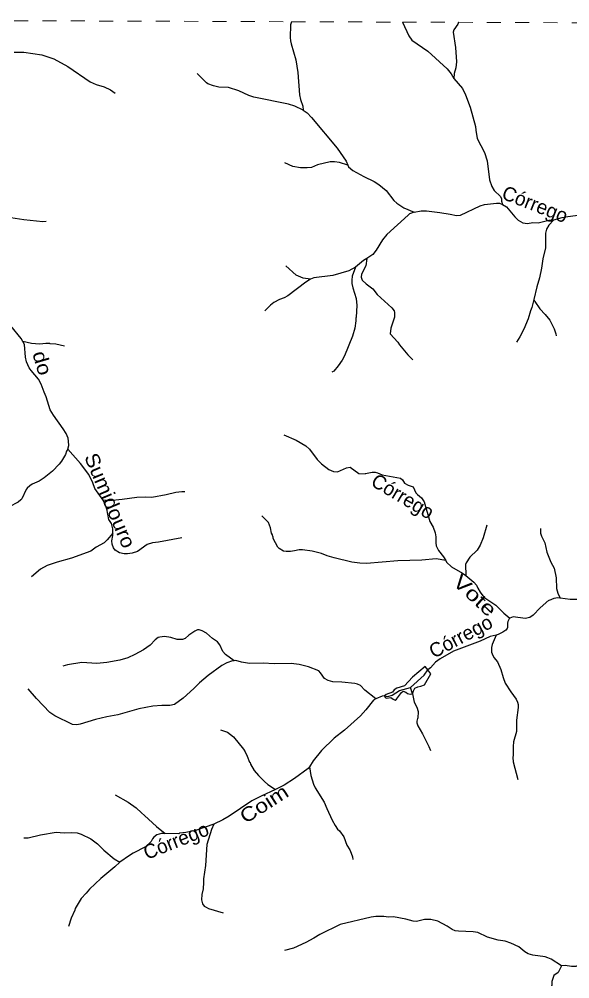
# Model space of a CAD drawing. Extents: x 551.6 to 577.6, y 7567 to 7594.7.
# Drawn here: x 554.66 to 558.55, y 7587.95 to 7594.73 of the extents above; entities that cross this region are included whole.
import ezdxf
from ezdxf.enums import TextEntityAlignment as Align

# ---------------------------------------------------------------- set-up
doc = ezdxf.new("R2010")
doc.units = 0
doc.header["$LTSCALE"] = 0.04
doc.linetypes.add('SHORT_DASHED', pattern=[2.7, 1.5, -1.2])
for name, color, linetype, lineweight in [('2', 7, 'Continuous', 25), ('53', 7, 'SHORT_DASHED', 13), ('55', 7, 'Continuous', 25), ('7', 7, 'Continuous', 25)]:
    doc.layers.add(name, color=color, linetype=linetype, lineweight=lineweight)
doc.layers.add('61', color=7, linetype='Continuous')

msp = doc.modelspace()

# ---------------------------------------------------------------- linework, layer by layer
at = {"layer": '2'}
msp.add_line((557.5713, 7590.1064), (557.5493, 7590.1345), dxfattribs=at)
for points in [[(557.5493, 7590.1345), (557.5317, 7590.1571), (557.4418, 7590.0815), (557.3847, 7590.0219), (557.3307, 7590.0034), (557.3108, 7589.9927), (557.2997, 7589.9763), (557.2557, 7589.9592), (557.2445, 7589.9499)], [(557.4425, 7589.9644), (557.4481, 7589.9864), (557.4578, 7590.005), (557.4779, 7590.0146), (557.4997, 7590.0179), (557.5255, 7590.0292), (557.5713, 7590.1064)], [(557.2445, 7589.9499), (557.2476, 7589.9376), (557.2587, 7589.9331), (557.2885, 7589.9383), (557.3041, 7589.9264), (557.3195, 7589.9208), (557.3284, 7589.9275), (557.3626, 7589.9751), (557.376, 7589.9841), (557.3939, 7589.9766), (557.4058, 7589.9662), (557.4244, 7589.9625), (557.4425, 7589.9644)]]:
    msp.add_lwpolyline(points, dxfattribs=at)
at = {"layer": '53'}
msp.add_lwpolyline([(551.6503, 7578.541), (551.6589, 7581.176), (551.6615, 7581.9586), (551.6634, 7582.5573), (551.6645, 7582.8996), (551.6852, 7589.2613), (551.6863, 7589.5882), (551.6896, 7590.6141), (551.6917, 7591.2598), (551.6958, 7592.5139), (551.6971, 7592.9033), (551.701, 7594.113), (551.703, 7594.7296), (552.7903, 7594.7256), (553.4424, 7594.7233), (554.6279, 7594.7189), (556.5859, 7594.7118), (557.3702, 7594.7089), (557.7663, 7594.7075), (559.9893, 7594.6994)], dxfattribs=at)
at = {"layer": '55'}
msp.add_line((557.4425, 7589.9644), (557.4269, 7590.0083), dxfattribs=at)
for points in [[(557.4269, 7590.0083), (557.5233, 7590.0957), (557.549, 7590.1343)], [(557.2445, 7589.9499), (557.2669, 7589.9451), (557.2974, 7589.954), (557.3502, 7589.9883), (557.4269, 7590.0083)]]:
    msp.add_lwpolyline(points, dxfattribs=at)
at = {"layer": '7'}
for points in [[(556.5859, 7594.7118), (556.579, 7594.689), (556.5782, 7594.6004), (556.5806, 7594.5779), (556.5839, 7594.5554), (556.6177, 7594.4427), (556.6305, 7594.3526), (556.6434, 7594.1964), (556.6499, 7594.1626), (556.666, 7594.1143), (556.668, 7594.088)], [(557.3702, 7594.7089), (557.416, 7594.6117), (557.4378, 7594.5819), (557.5504, 7594.503), (557.6864, 7594.3799), (557.7146, 7594.3437), (557.7339, 7594.311)], [(557.7663, 7594.7075), (557.7613, 7594.6954), (557.7331, 7594.6535), (557.7283, 7594.6375), (557.7444, 7594.5296), (557.7532, 7594.4282), (557.7476, 7594.3864), (557.7347, 7594.3469), (557.7339, 7594.311)], [(554.6282, 7594.4974), (554.6958, 7594.4974), (554.8246, 7594.4781), (554.9075, 7594.4507), (555.0065, 7594.3944), (555.1642, 7594.2874), (555.2077, 7594.268), (555.264, 7594.252), (555.3091, 7594.2302), (555.3421, 7594.2077)], [(556.668, 7594.088), (556.6096, 7594.1143), (556.5646, 7594.1304), (556.3199, 7594.1787), (556.2861, 7594.1908), (556.2137, 7594.2238), (556.1412, 7594.2463), (556.0736, 7594.2487), (556.035, 7594.2584), (555.9964, 7594.2737), (555.9875, 7594.2801), (555.9199, 7594.3453)], [(557.7339, 7594.311), (557.7951, 7594.2399), (557.8168, 7594.1948), (557.849, 7594.1079), (557.886, 7593.9711), (557.8876, 7593.9453)], [(556.668, 7594.088), (556.6973, 7594.0676), (556.7279, 7594.0355), (556.909, 7593.8182)], [(557.8876, 7593.9453), (557.8989, 7593.8874), (557.9488, 7593.7884), (557.9681, 7593.7297), (557.9858, 7593.5961), (558.0019, 7593.5478), (558.0188, 7593.5188), (558.0631, 7593.4777), (558.0695, 7593.4608), (558.0695, 7593.4448), (558.0773, 7593.4201)], [(556.909, 7593.8182), (556.9718, 7593.7272), (556.9843, 7593.6994)], [(556.9843, 7593.6994), (556.9251, 7593.7168), (556.8897, 7593.7216), (556.8607, 7593.7216), (556.7706, 7593.7015), (556.7271, 7593.683), (556.6982, 7593.6789), (556.6499, 7593.6789), (556.5952, 7593.6886), (556.5396, 7593.7152)], [(556.9843, 7593.6994), (556.9895, 7593.6878), (557.0201, 7593.662), (557.0973, 7593.6186), (557.1698, 7593.5832), (557.2044, 7593.5614), (557.2551, 7593.5188), (557.309, 7593.448), (557.3299, 7593.4294), (557.3798, 7593.3981), (557.4531, 7593.3675)], [(557.7074, 7593.3514), (557.7525, 7593.3433), (557.7814, 7593.3449), (557.9199, 7593.4109), (557.9488, 7593.4198), (558.0357, 7593.4311), (558.0551, 7593.4294), (558.0773, 7593.4201)], [(554.8544, 7593.2999), (554.8294, 7593.2991), (554.6974, 7593.3119), (554.5751, 7593.3321), (554.5091, 7593.3313), (554.4158, 7593.3192), (554.3192, 7593.3111), (554.295, 7593.3144), (554.1517, 7593.3627)], [(557.4531, 7593.3675), (557.4209, 7593.3546), (557.4096, 7593.3465), (557.2607, 7593.2089), (557.2301, 7593.1711), (557.185, 7593.0987), (557.1601, 7593.0673), (557.1191, 7593.0385)], [(557.4531, 7593.3675), (557.5014, 7593.3763), (557.54, 7593.3763), (557.635, 7593.3651), (557.7074, 7593.3514)], [(558.0773, 7593.4201), (558.1041, 7593.4045), (558.1645, 7593.3345), (558.1887, 7593.3111), (558.2208, 7593.2918), (558.253, 7593.2854), (558.2901, 7593.2942), (558.3287, 7593.2902), (558.4043, 7593.3095), (558.4398, 7593.3133)], [(558.5379, 7593.3353), (558.6474, 7593.3498), (558.6715, 7593.3578), (558.7053, 7593.3755), (558.7343, 7593.382), (558.7496, 7593.382), (558.8228, 7593.3465), (558.8518, 7593.3417), (558.8808, 7593.3433), (558.9267, 7593.3549), (558.9452, 7593.3578)], [(558.4398, 7593.3133), (558.4051, 7593.2749), (558.3874, 7593.2468), (558.3818, 7593.2194), (558.3802, 7593.1148), (558.3617, 7593.0375), (558.3528, 7592.9699), (558.3383, 7592.9039), (558.319, 7592.8395), (558.2975, 7592.7506)], [(558.4398, 7593.3133), (558.4993, 7593.3296), (558.5379, 7593.3353)], [(557.1191, 7593.0385), (557.0957, 7593.0246), (557.0383, 7592.9781)], [(557.1191, 7593.0385), (557.1118, 7592.9876), (557.0812, 7592.9297), (557.0796, 7592.9071), (557.086, 7592.887), (557.1151, 7592.8596), (557.1609, 7592.8259), (557.1915, 7592.784), (557.2953, 7592.6898), (557.3114, 7592.6689), (557.3146, 7592.6577), (557.3146, 7592.6239), (557.2873, 7592.5466), (557.284, 7592.508), (557.3372, 7592.4484), (557.3484, 7592.4307), (557.408, 7592.3583), (557.4426, 7592.3237)], [(556.7215, 7592.8942), (556.6692, 7592.8999), (556.6193, 7592.9208), (556.5461, 7592.9868)], [(557.0383, 7592.9781), (556.9911, 7592.953), (556.8784, 7592.92), (556.7448, 7592.9023), (556.7215, 7592.8942)], [(557.0383, 7592.9781), (557.0152, 7592.9136), (557.012, 7592.8862), (557.0136, 7592.8621), (557.0201, 7592.8331), (557.0426, 7592.7558), (557.0474, 7592.7076), (557.0442, 7592.6247), (557.041, 7592.6174), (557.0418, 7592.5997), (557.0329, 7592.5466), (557.0185, 7592.4903), (556.9621, 7592.3518), (556.9444, 7592.3204), (556.9154, 7592.2802), (556.8865, 7592.244), (556.8728, 7592.2359)], [(554.6901, 7592.4524), (554.6765, 7592.4749), (554.6057, 7592.5627), (554.5067, 7592.6472), (554.4672, 7592.6931), (554.4109, 7592.747), (554.3546, 7592.7896), (554.2403, 7592.8677), (554.15, 7592.9437)], [(556.7215, 7592.8942), (556.6885, 7592.8733), (556.5597, 7592.7751), (556.534, 7592.7615), (556.5018, 7592.7502), (556.4615, 7592.7277)], [(556.4615, 7592.7277), (556.4374, 7592.7108), (556.398, 7592.6697)], [(558.2975, 7592.7506), (558.2836, 7592.6931), (558.2739, 7592.6689), (558.2587, 7592.6126), (558.2281, 7592.5402), (558.1999, 7592.4854), (558.1766, 7592.4492)], [(558.2975, 7592.7506), (558.3045, 7592.7349), (558.3399, 7592.6834), (558.3786, 7592.6448), (558.4124, 7592.6045), (558.4414, 7592.5425), (558.4534, 7592.5064), (558.455, 7592.4927)], [(554.7087, 7592.3422), (554.7022, 7592.4323), (554.6901, 7592.4524)], [(554.9831, 7592.4194), (554.9228, 7592.4331), (554.8833, 7592.4363), (554.8809, 7592.4395), (554.852, 7592.4395), (554.8085, 7592.4339), (554.7795, 7592.4355), (554.7505, 7592.4387), (554.6901, 7592.4524)], [(555.007, 7591.6931), (555.0152, 7591.7177), (555.0129, 7591.7482), (555.0097, 7591.7692), (554.9952, 7591.803), (554.9751, 7591.8368), (554.9067, 7591.9317), (554.8833, 7591.9704), (554.8543, 7592.0621), (554.8391, 7592.0959), (554.8197, 7592.1522), (554.8004, 7592.186), (554.7473, 7592.2488), (554.7344, 7592.2681), (554.7151, 7592.3084), (554.7087, 7592.3422)], [(556.5332, 7591.7949), (556.6193, 7591.7555), (556.6877, 7591.7152), (556.7134, 7591.6919), (556.7674, 7591.6203), (556.7979, 7591.5881), (556.8495, 7591.5486), (556.8833, 7591.5341), (556.9106, 7591.5325), (556.975, 7591.5615), (557.0008, 7591.5663), (557.0619, 7591.5213), (557.107, 7591.5188), (557.1086, 7591.5213), (557.1569, 7591.5293), (557.1778, 7591.5293), (557.1939, 7591.5261), (557.2277, 7591.5116), (557.3565, 7591.4882)], [(555.007, 7591.6931), (554.9976, 7591.6774), (554.9896, 7591.6549), (554.963, 7591.6082), (554.9469, 7591.5864), (554.8986, 7591.5382), (554.8391, 7591.4899), (554.8037, 7591.4673), (554.7562, 7591.4456), (554.7393, 7591.4343), (554.7199, 7591.4167), (554.7135, 7591.407), (554.6821, 7591.3426), (554.6749, 7591.3345), (554.6572, 7591.3193), (554.5936, 7591.2863), (554.5735, 7591.2654), (554.5606, 7591.2428), (554.5477, 7591.201), (554.5397, 7591.1623), (554.5389, 7591.1237), (554.5123, 7591.0464), (554.4978, 7590.9869), (554.493, 7590.9507)], [(555.2578, 7591.3329), (555.198, 7591.4142), (555.1843, 7591.4553), (555.1545, 7591.5132), (555.0974, 7591.5913), (555.007, 7591.6931)], [(557.3565, 7591.4882), (557.3709, 7591.4762), (557.3846, 7591.4521), (557.4112, 7591.4376), (557.445, 7591.4263), (557.4643, 7591.3853), (557.4756, 7591.3716), (557.5038, 7591.349), (557.5247, 7591.3201), (557.5633, 7591.1817), (557.5883, 7591.1414), (557.6011, 7591.1028), (557.606, 7591.0738), (557.606, 7591.032), (557.6092, 7591.0094), (557.6261, 7590.9772), (557.6607, 7590.9314), (557.6763, 7590.9052)], [(555.8346, 7591.3909), (555.8113, 7591.3917), (555.7694, 7591.3861), (555.7018, 7591.3692), (555.6004, 7591.3523), (555.5553, 7591.3547), (555.4942, 7591.3523), (555.3912, 7591.3362), (555.2994, 7591.3289), (555.2578, 7591.3329)], [(555.3252, 7591.1003), (555.3252, 7591.1301), (555.3155, 7591.1672), (555.2962, 7591.1953), (555.2817, 7591.2718), (555.2688, 7591.3056), (555.2578, 7591.3329)], [(556.608, 7590.9756), (556.5791, 7590.9692), (556.5501, 7590.9692), (556.5308, 7590.9724), (556.5002, 7590.9901), (556.4913, 7591.0014), (556.4583, 7591.0625), (556.4583, 7591.0746), (556.4551, 7591.0754), (556.4535, 7591.0867), (556.4454, 7591.0988), (556.4374, 7591.1366), (556.4237, 7591.1752), (556.3762, 7591.2211)], [(557.9657, 7591.1567), (557.9416, 7591.0658), (557.919, 7591.0143), (557.8973, 7590.9796), (557.8474, 7590.9305), (557.8192, 7590.8887), (557.8168, 7590.879), (557.8184, 7590.7999)], [(558.3448, 7591.1326), (558.3448, 7591.0996), (558.352, 7591.077), (558.3753, 7591.032), (558.389, 7590.9644), (558.4188, 7590.8951), (558.4413, 7590.8533), (558.4566, 7590.7841), (558.459, 7590.7084), (558.4687, 7590.6746), (558.4841, 7590.6393)], [(555.3252, 7591.1003), (555.2849, 7591.0521), (555.2632, 7591.0311), (555.2061, 7590.9998), (555.169, 7590.9732), (555.0322, 7590.9225), (554.9308, 7590.8951), (554.86, 7590.8718), (554.8133, 7590.8452), (554.7513, 7590.7913)], [(555.8121, 7591.0658), (555.6471, 7591.036), (555.6052, 7591.0311), (555.5666, 7591.0199), (555.499, 7590.9708), (555.4604, 7590.9579), (555.4282, 7590.9523), (555.404, 7590.9531), (555.3719, 7590.9595), (555.3413, 7590.9804), (555.33, 7590.9949), (555.3203, 7591.0207), (555.3179, 7591.0448), (555.3251, 7591.0826), (555.3252, 7591.1003)], [(557.6763, 7590.9052), (557.6076, 7590.9177), (557.5078, 7590.9096), (557.3372, 7590.9048), (557.1167, 7590.8855), (557.0684, 7590.8871), (557.0136, 7590.8935), (556.8881, 7590.9241), (556.8382, 7590.9386), (556.798, 7590.9547), (556.732, 7590.9724), (556.6644, 7590.982), (556.6418, 7590.982), (556.608, 7590.9756)], [(557.6763, 7590.9052), (557.6824, 7590.8951), (557.7162, 7590.8605), (557.7943, 7590.8179), (557.8184, 7590.7999)], [(557.8184, 7590.7999), (557.8756, 7590.7527), (557.8933, 7590.731), (557.9037, 7590.71)], [(557.9037, 7590.71), (557.9182, 7590.6819), (557.9456, 7590.6472), (558.0309, 7590.5909), (558.0872, 7590.5338), (558.1283, 7590.5)], [(558.4841, 7590.6393), (558.4687, 7590.6424), (558.4398, 7590.6384), (558.4075, 7590.6239), (558.4046, 7590.625), (558.3424, 7590.5724), (558.2941, 7590.5201), (558.2691, 7590.504), (558.2369, 7590.4976), (558.1532, 7590.5088), (558.1283, 7590.5), (558.1243, 7590.4935)], [(558.8969, 7590.5024), (558.8679, 7590.504), (558.8389, 7590.5137), (558.8083, 7590.5281), (558.7713, 7590.5571), (558.7118, 7590.5611), (558.6932, 7590.5748), (558.6747, 7590.6006), (558.6595, 7590.6159), (558.6273, 7590.632), (558.554, 7590.6312), (558.4841, 7590.6393)], [(558.1243, 7590.4935), (558.1146, 7590.475), (558.1122, 7590.4638), (558.113, 7590.4332), (558.1098, 7590.4251), (558.1001, 7590.4138), (558.0792, 7590.3994), (558.0454, 7590.3825), (558.0322, 7590.3794)], [(556.1817, 7590.1986), (556.1203, 7590.2433), (556.1018, 7590.2642), (556.0817, 7590.31), (556.064, 7590.3318), (556.0294, 7590.3543), (555.9867, 7590.3937), (555.9561, 7590.4098), (555.9352, 7590.4163), (555.9239, 7590.4155), (555.903, 7590.4074), (555.8612, 7590.3784), (555.8354, 7590.3551), (555.8169, 7590.3479), (555.7791, 7590.3479), (555.734, 7590.3623), (555.6906, 7590.3688), (555.6568, 7590.3656), (555.6455, 7590.3615), (555.6245, 7590.3471), (555.5875, 7590.3076), (555.5425, 7590.2746), (555.4797, 7590.2424), (555.4298, 7590.2199), (555.3735, 7590.203), (555.2817, 7590.1869)], [(558.0322, 7590.3794), (557.9907, 7590.3696), (557.9199, 7590.3358), (557.7299, 7590.265), (557.6366, 7590.2118), (557.6044, 7590.1877), (557.5673, 7590.1483), (557.5493, 7590.1345), (557.549, 7590.1343)], [(558.0322, 7590.3794), (558.0035, 7590.3125), (558.0003, 7590.2915), (558.0003, 7590.2577), (558.0035, 7590.2465), (558.0164, 7590.2223), (558.0414, 7590.1901), (558.0647, 7590.137), (558.0808, 7590.0791), (558.0961, 7590.0388), (558.1347, 7589.9785), (558.1725, 7589.9277), (558.1838, 7589.9068), (558.187, 7589.8891), (558.187, 7589.8682), (558.1758, 7589.7797), (558.1758, 7589.6992), (558.1548, 7589.6252), (558.1516, 7589.593), (558.1516, 7589.5318)], [(555.2817, 7590.1869), (555.2109, 7590.1781), (555.1063, 7590.1853), (555.0049, 7590.1684), (554.9719, 7590.1596)], [(556.1817, 7590.1986), (556.1694, 7590.1982), (556.1308, 7590.1837), (556.0946, 7590.1636), (555.9988, 7590.0935), (555.9368, 7590.0412), (555.8974, 7590.0018), (555.8209, 7589.9334), (555.7606, 7589.8883), (555.7276, 7589.8811), (555.6712, 7589.8811), (555.6069, 7589.8763), (555.5095, 7589.8594), (555.3606, 7589.8167), (555.2817, 7589.803)], [(556.2346, 7590.1885), (556.1944, 7590.199), (556.1817, 7590.1986)], [(557.1826, 7589.9294), (557.1046, 7589.9914), (557.0748, 7590.0227), (557.0523, 7590.0324), (557.033, 7590.0364), (556.9428, 7590.0469), (556.8784, 7590.0501), (556.8446, 7590.0597), (556.8189, 7590.0718), (556.7923, 7590.1137), (556.7794, 7590.1273), (556.7062, 7590.1563), (556.6402, 7590.1708), (556.5839, 7590.1789), (556.4632, 7590.1772), (556.3875, 7590.1805), (556.2893, 7590.1797), (556.2346, 7590.1885)], [(555.2817, 7589.803), (555.2028, 7589.7829), (555.0934, 7589.7499), (555.0709, 7589.7459), (555.0411, 7589.7483), (554.9163, 7589.8094), (554.8801, 7589.8328), (554.7868, 7589.931), (554.7264, 7590.001)], [(557.1826, 7589.9294), (557.1665, 7589.9205), (557.1118, 7589.8521), (557.0732, 7589.8103), (556.9621, 7589.7088), (556.8889, 7589.6517), (556.7987, 7589.5632), (556.74, 7589.4916), (556.7136, 7589.4486)], [(557.2445, 7589.9499), (557.2261, 7589.9487), (557.1826, 7589.9294)], [(557.4425, 7589.9644), (557.4522, 7589.9052), (557.4716, 7589.8698), (557.482, 7589.8409), (557.4788, 7589.7934), (557.4756, 7589.791), (557.4724, 7589.7716), (557.4724, 7589.7604), (557.4788, 7589.7378), (557.5118, 7589.6815), (557.5569, 7589.593), (557.5673, 7589.5632)], [(556.0857, 7589.7105), (556.1348, 7589.6928), (556.1774, 7589.6606), (556.2466, 7589.5737), (556.2587, 7589.5543), (556.2748, 7589.5254), (556.2909, 7589.4819), (556.2942, 7589.4803), (556.2982, 7589.4674), (556.3239, 7589.4232), (556.3545, 7589.3869), (556.3964, 7589.3451), (556.4197, 7589.325), (556.4745, 7589.2886)], [(558.1516, 7589.5318), (558.15, 7589.5157), (558.1532, 7589.4835), (558.1854, 7589.3604)], [(556.7136, 7589.4486), (556.7046, 7589.436), (556.608, 7589.366), (556.534, 7589.3201), (556.4745, 7589.2886), (556.3714, 7589.2421)], [(556.7136, 7589.4486), (556.7239, 7589.387), (556.7424, 7589.3258), (556.7537, 7589.3), (556.8181, 7589.1986), (556.8358, 7589.1536), (556.8736, 7589.0731), (556.8953, 7589.0344), (556.9122, 7589.0095), (556.9267, 7588.9966), (556.9565, 7588.954), (556.9782, 7588.896), (556.9991, 7588.8622), (557.0088, 7588.8397), (557.0177, 7588.8139), (557.0201, 7588.7938)], [(555.3405, 7589.2509), (555.4338, 7589.1986), (555.4901, 7589.16), (555.5264, 7589.123), (555.5497, 7589.1061), (555.6334, 7589.028), (555.6942, 7588.9784)], [(556.3714, 7589.2421), (556.3078, 7589.2083), (556.1469, 7589.1004), (556.1026, 7589.0739), (556.0379, 7589.0448)], [(556.0379, 7589.0448), (555.9095, 7588.9998), (555.8402, 7588.9845), (555.7968, 7588.9797), (555.7911, 7588.9765), (555.6942, 7588.9784)], [(556.0379, 7589.0448), (556.0213, 7589.0055), (555.9899, 7588.9009), (555.9803, 7588.7512), (555.9642, 7588.6578), (555.9658, 7588.632), (555.9626, 7588.587), (555.9529, 7588.5483), (555.9513, 7588.5097), (555.9593, 7588.4807), (555.9706, 7588.4654), (555.9843, 7588.4566), (556.0004, 7588.4477), (556.105, 7588.4172)], [(554.6966, 7588.9475), (554.728, 7588.9483), (554.8149, 7588.9684), (554.9244, 7588.9886), (554.9807, 7588.9829), (555.0338, 7588.9861), (555.0725, 7588.9829), (555.1022, 7588.9733), (555.169, 7588.9395), (555.2173, 7588.9041), (555.2608, 7588.8598), (555.334, 7588.8002), (555.3748, 7588.7763)], [(555.6942, 7588.9784), (555.6696, 7588.9789), (555.6358, 7588.9684), (555.6149, 7588.9531), (555.6044, 7588.9411), (555.5956, 7588.921), (555.5561, 7588.8839), (555.4676, 7588.8397), (555.4427, 7588.8236), (555.3748, 7588.7763)], [(555.3748, 7588.7763), (555.3397, 7588.7415), (555.2406, 7588.6594), (555.161, 7588.5854), (555.1377, 7588.5564), (555.1006, 7588.5186), (555.058, 7588.4486), (555.0556, 7588.4373), (555.0306, 7588.381), (555.0129, 7588.3206)], [(557.445, 7588.3584), (557.3935, 7588.3729), (557.3066, 7588.389), (557.2728, 7588.3874), (557.239, 7588.3922), (557.1827, 7588.3922), (557.1489, 7588.3866), (556.9299, 7588.3343), (556.7867, 7588.2658), (556.7448, 7588.2377), (556.6885, 7588.2087), (556.6, 7588.1685), (556.5364, 7588.1524)], [(558.4947, 7588.043), (558.4204, 7588.0904), (558.3979, 7588.1009), (558.3786, 7588.1073), (558.2917, 7588.1186), (558.2579, 7588.1282), (558.2337, 7588.1411), (558.1919, 7588.1773), (558.1355, 7588.2039), (558.0953, 7588.2168), (558.047, 7588.2248), (557.9714, 7588.2465), (557.9038, 7588.2779), (557.87, 7588.2836), (557.7653, 7588.2876), (557.7428, 7588.2916), (557.7211, 7588.2996), (557.6872, 7588.323), (557.6205, 7588.36), (557.5706, 7588.3705), (557.5255, 7588.3697), (557.4692, 7588.3568), (557.445, 7588.3584)], [(558.843, 7588.0912), (558.8148, 7588.0759), (558.7649, 7588.0638), (558.7198, 7588.0671), (558.645, 7588.0815), (558.6305, 7588.0687), (558.616, 7588.0494), (558.5959, 7588.0381), (558.5637, 7588.0381), (558.5202, 7588.0461), (558.4947, 7588.043)], [(558.4947, 7588.043), (558.4711, 7587.9954), (558.4397, 7587.9745), (558.4365, 7587.9689), (558.4252, 7587.9335), (558.4252, 7587.9077), (558.4212, 7587.8949), (558.4019, 7587.8602), (558.3802, 7587.8393), (558.3673, 7587.8353), (558.3222, 7587.8337), (558.2917, 7587.8119), (558.2651, 7587.7846), (558.253, 7587.7781), (558.245, 7587.7757), (558.2208, 7587.7789), (558.2023, 7587.7733), (558.183, 7587.7564), (558.1693, 7587.7387), (558.1661, 7587.7266), (558.1484, 7587.7017), (558.1123, 7587.6688)]]:
    msp.add_lwpolyline(points, dxfattribs=at)

# ---------------------------------------------------------------- texts
at = {"layer": '61'}
for rotation, p in [(338.594, (558.2887, 7593.3763)), (329.204, (557.347, 7591.317)), (28.017, (557.8049, 7590.3256)), (21.848, (555.7898, 7588.8811))]:
    msp.add_text('Córrego', height=0.1, rotation=rotation, dxfattribs=at).set_placement(p, align=Align.CENTER)
for s, rotation, width, p in [('do', 286.339, 1.15, (554.7794, 7592.2874)), ('Sumidouro', 292.875, 1.1, (555.2595, 7591.3109)), ('Vote', 317.059, 1.3, (557.8482, 7590.6222)), ('Coim', 32.726, 1.2, (556.4198, 7589.145))]:
    msp.add_text(s, height=0.1, rotation=rotation, dxfattribs=dict(at, width=width)).set_placement(p, align=Align.CENTER)

doc.saveas('drawing.dxf')
